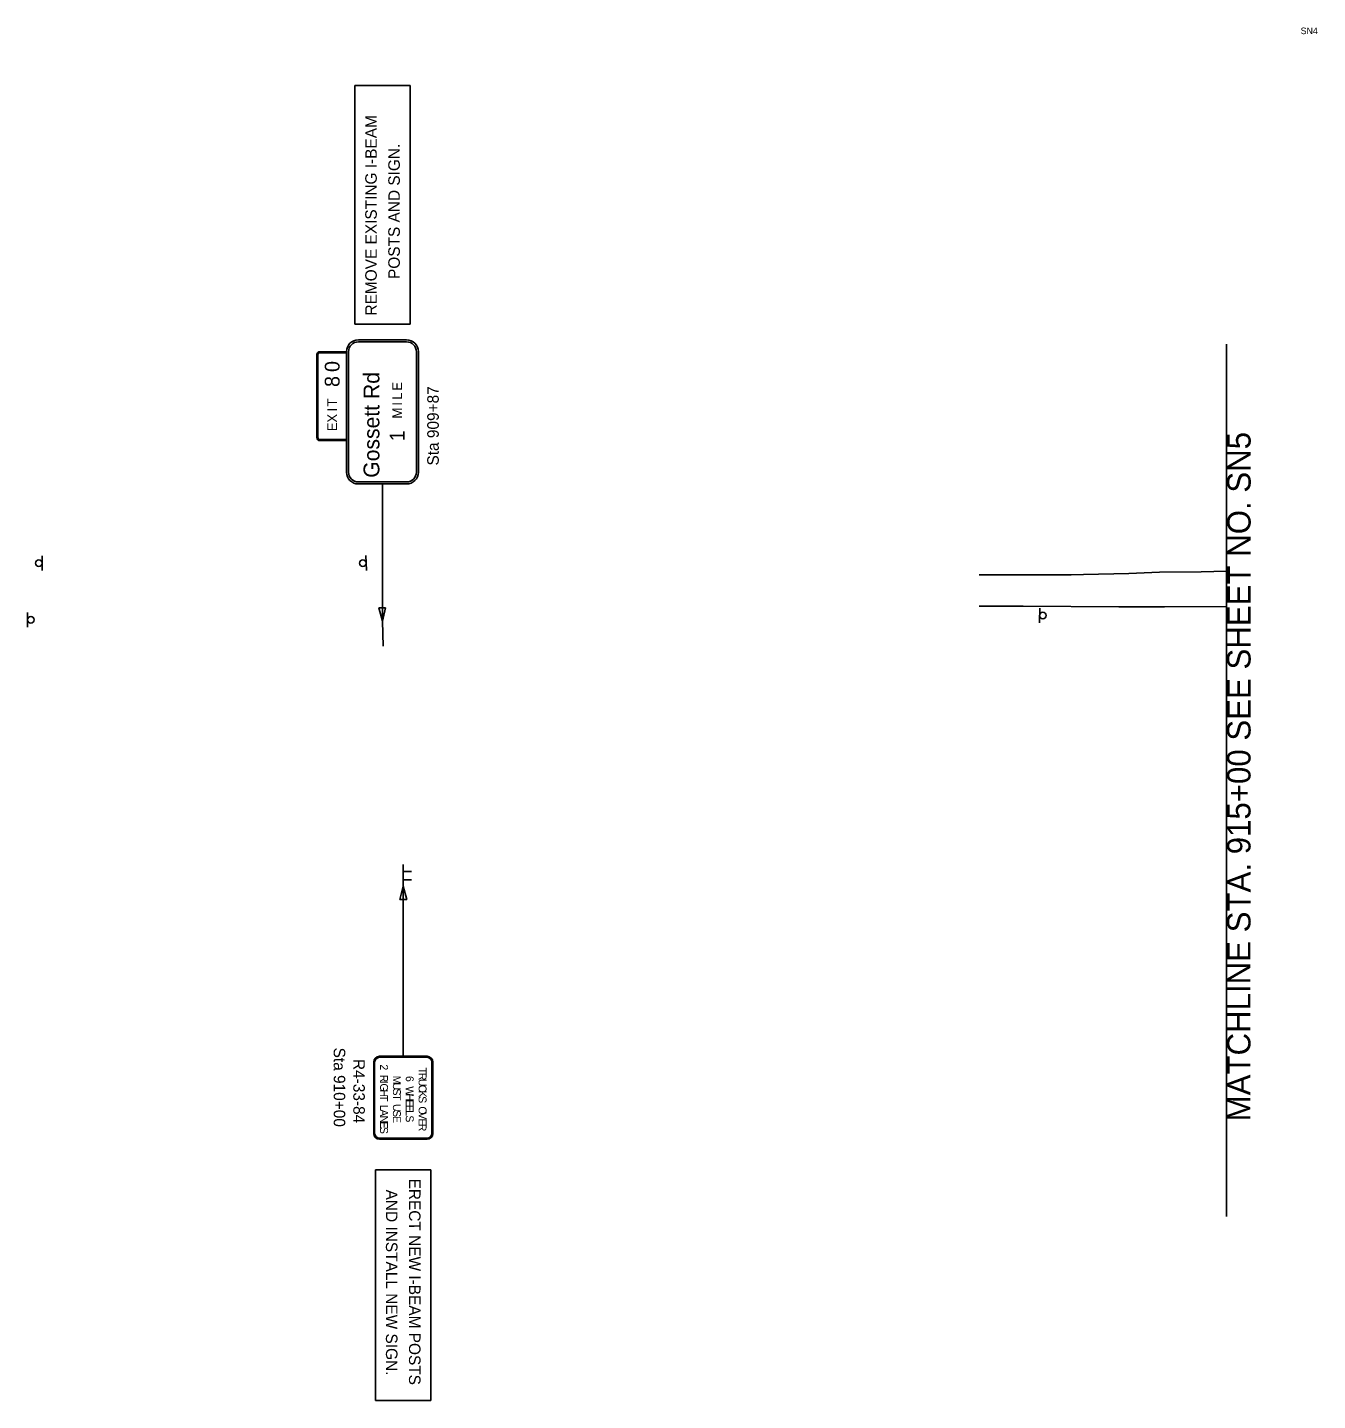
# Model space of a CAD drawing. Extents: x 1738774 to 1740359, y 1166808 to 1167650.
# Drawn here: x 1739575 to 1740359, y 1166808 to 1167642 of the extents above; entities that cross this region are included whole.
import ezdxf

# ---------------------------------------------------------------- set-up
doc = ezdxf.new("R2010")
doc.units = 0
for name, color, linetype in [('RD_EX_Road', 7, 'Continuous'), ('RD_SHT_MatchLine', 7, 'Continuous'), ('RD_SHT_TX', 7, 'Continuous'), ('SN_P_Signs', 7, 'Continuous')]:
    doc.layers.add(name, color=color, linetype=linetype)

msp = doc.modelspace()

# ---------------------------------------------------------------- linework, layer by layer
at = {"layer": 'RD_EX_Road'}
for points in [[(1740303.73, 1167311.86), (1740288.33, 1167311.47), (1740263.02, 1167311.09), (1740244.51, 1167310.39), (1740216.78, 1167309.74), (1740209.34, 1167309.56), (1740178.78, 1167309.55), (1740161.18, 1167309.54), (1740153.46, 1167309.6)], [(1740153.47, 1167290.46), (1740180.3, 1167290.45), (1740238.29, 1167290.17), (1740266.1, 1167290.17), (1740303.73, 1167290.28)]]:
    msp.add_lwpolyline(points, dxfattribs=at)
at = {"layer": 'RD_SHT_MatchLine'}
msp.add_lwpolyline([(1740303.73, 1166919.91), (1740303.73, 1167194.04), (1740303.73, 1167449.62)], dxfattribs=at)
at = {"layer": 'SN_P_Signs'}
for p, q in [((1739774.26, 1167461.8), (1739774.26, 1167606.82)), ((1739774.26, 1167606.82), (1739807.87, 1167606.82)), ((1739807.87, 1167606.82), (1739807.87, 1167461.8)), ((1739807.87, 1167461.8), (1739774.26, 1167461.8)), ((1739791.07, 1167364.75), (1739791.07, 1167281.39)), ((1739584.35, 1167312.12), (1739584.35, 1167321.12)), ((1739781.31, 1167312.23), (1739780.97, 1167321.23)), ((1740190.28, 1167289.39), (1740190.13, 1167280.39)), ((1739575.45, 1167286.77), (1739575.56, 1167277.77)), ((1739791.43, 1167266.17), (1739791.07, 1167281.39)), ((1739803.73, 1167120.52), (1739803.73, 1167133.56)), ((1739803.73, 1167129.45), (1739808.72, 1167129.45)), ((1739803.73, 1167124.43), (1739808.72, 1167124.43)), ((1739803.73, 1167017.16), (1739803.73, 1167120.52)), ((1739786.93, 1166808.11), (1739786.93, 1166948.13)), ((1739786.93, 1166948.13), (1739820.54, 1166948.13)), ((1739820.54, 1166948.13), (1739820.54, 1166808.11)), ((1739820.54, 1166808.11), (1739786.93, 1166808.11))]:
    msp.add_line(p, q, dxfattribs=at)
for points in [[(1739776.43, 1167452.27), (1739805.7, 1167452.27)], [(1739776.43, 1167451.07), (1739805.7, 1167451.07)], [(1739751.23, 1167392.87), (1739751.23, 1167443.27)], [(1739751.83, 1167443.27), (1739751.83, 1167392.87)], [(1739753.03, 1167445.07), (1739769.23, 1167445.07), (1739769.23, 1167444.47)], [(1739769.23, 1167444.47), (1739753.03, 1167444.47)], [(1739769.23, 1167371.95), (1739769.23, 1167445.07)], [(1739770.43, 1167371.95), (1739770.43, 1167445.07)], [(1739811.7, 1167445.07), (1739811.7, 1167371.95)], [(1739812.9, 1167445.07), (1739812.9, 1167371.95)], [(1739753.03, 1167391.67), (1739769.23, 1167391.67), (1739769.23, 1167391.07), (1739753.03, 1167391.07)], [(1739805.7, 1167365.95), (1739776.43, 1167365.95)], [(1739805.7, 1167364.75), (1739776.43, 1167364.75)], [(1739818.13, 1167017.16), (1739789.33, 1167017.16)], [(1739789.33, 1167016.56), (1739818.13, 1167016.56)], [(1739785.73, 1167013.56), (1739785.73, 1166970.36)], [(1739786.33, 1166970.36), (1739786.33, 1167013.56)], [(1739821.13, 1167013.56), (1739821.13, 1166970.36)], [(1739821.73, 1166970.36), (1739821.73, 1167013.56)], [(1739818.13, 1166967.36), (1739789.33, 1166967.36)], [(1739789.33, 1166966.76), (1739818.13, 1166966.76)]]:
    msp.add_lwpolyline(points, dxfattribs=at)
for points in [[(1739792.98, 1167289.62), (1739791.02, 1167281.39), (1739788.88, 1167289.57)], [(1739801.68, 1167112.32), (1739803.73, 1167120.52), (1739805.79, 1167112.32)]]:
    msp.add_lwpolyline(points, close=True, dxfattribs=at)
for centre in [(1739582.33, 1167316.64), (1739779.12, 1167316.67), (1739577.53, 1167282.28), (1740192.23, 1167284.84)]:
    msp.add_circle(centre, 2, dxfattribs=at)
for centre, radius, start, end in [((1739776.43, 1167445.07), 7.2, 90, 180), ((1739776.43, 1167445.07), 6, 90, 180), ((1739805.7, 1167445.07), 7.2, 360, 90), ((1739805.7, 1167445.07), 6, 360, 90), ((1739753.03, 1167443.27), 1.8, 90, 180), ((1739753.03, 1167443.27), 1.2, 90, 180), ((1739753.03, 1167392.87), 1.8, 180, 270), ((1739753.03, 1167392.87), 1.2, 180, 270), ((1739776.43, 1167371.95), 7.2, 180, 270), ((1739776.43, 1167371.95), 6, 180, 270), ((1739805.7, 1167371.95), 7.2, 270, 360), ((1739805.7, 1167371.95), 6, 270, 360), ((1739789.33, 1167013.56), 3.6, 90, 180), ((1739789.33, 1167013.56), 3, 90, 180), ((1739818.13, 1167013.56), 3.6, 360, 90), ((1739818.13, 1167013.56), 3, 360, 90), ((1739789.33, 1166970.36), 3.6, 180, 270), ((1739789.33, 1166970.36), 3, 180, 270), ((1739818.13, 1166970.36), 3.6, 270, 360), ((1739818.13, 1166970.36), 3, 270, 360)]:
    msp.add_arc(centre, radius, start, end, dxfattribs=at)

# ---------------------------------------------------------------- texts
at = {"layer": 'RD_SHT_TX'}
msp.add_text('SN4', height=4, dxfattribs=at).set_placement((1740348.78, 1167637.92))
msp.add_text('MATCHLINE STA. 915+00 SEE SHEET NO. SN5', height=14.1726, rotation=89.98556, dxfattribs=at).set_placement((1740318.28, 1166977.67))
at = {"layer": 'SN_P_Signs'}
for s, height, rotation, p in [('REMOVE EXISTING I-BEAM', 6.9998, 90.00008, (1739787.62, 1167467.03)), ('POSTS AND SIGN.', 6.9998, 90.00008, (1739801.62, 1167489.22)), ('0', 9, 90, (1739765.03, 1167432.72)), ('Gossett Rd', 9.6, 90, (1739789.2, 1167368.52)), ('8', 9, 90, (1739765.03, 1167423.62)), ('E', 6, 90, (1739803, 1167421.32)), ('Sta 909+87', 7, 90.00008, (1739825.28, 1167375.93)), ('T', 6, 90, (1739763.53, 1167411.75)), ('L', 6, 90, (1739803, 1167415.89)), ('I', 6, 90, (1739763.53, 1167408.77)), ('X', 6, 90, (1739763.53, 1167401.95)), ('I', 6, 90, (1739803, 1167412.3)), ('M', 6, 90, (1739803, 1167404.44)), ('E', 6, 90, (1739763.53, 1167396.8)), ('1', 9, 90, (1739804.5, 1167390.69)), ('Sta 910+00', 7, 270.00008, (1739761.46, 1167022.44)), ('R4-33-84', 7, 270.00008, (1739773.36, 1167015.55)), ('2', 4.8, 270, (1739789.63, 1167012.25)), ('T', 4.8, 270, (1739813.03, 1167010.33)), ('R', 4.8, 270, (1739813.03, 1167007.12)), ('G', 4.8, 270, (1739789.63, 1167000.7)), ('R', 4.8, 270, (1739789.63, 1167006.02)), ('I', 4.8, 270, (1739789.63, 1167002.39)), ('U', 4.8, 270, (1739797.43, 1167001.27)), ('M', 4.8, 270, (1739797.43, 1167005.4)), ('6', 4.8, 270, (1739805.23, 1167005.23)), ('W', 4.8, 270, (1739805.23, 1166999)), ('U', 4.8, 270, (1739813.03, 1167003.48)), ('C', 4.8, 270, (1739813.03, 1166999.85)), ('H', 4.8, 270, (1739789.63, 1166997.07)), ('T', 4.8, 270, (1739789.63, 1166993.63)), ('S', 4.8, 270, (1739797.43, 1166997.64)), ('T', 4.8, 270, (1739797.43, 1166994.2)), ('H', 4.8, 270, (1739805.23, 1166994.59)), ('E', 4.8, 270, (1739805.23, 1166990.95)), ('S', 4.8, 270, (1739813.03, 1166992.98)), ('K', 4.8, 270, (1739813.03, 1166996.41)), ('L', 4.8, 270, (1739789.63, 1166987.63)), ('A', 4.8, 270, (1739789.63, 1166984.96)), ('U', 4.8, 270, (1739797.43, 1166988.2)), ('S', 4.8, 270, (1739797.43, 1166984.56)), ('S', 4.8, 270, (1739805.23, 1166981.32)), ('E', 4.8, 270, (1739805.23, 1166987.74)), ('L', 4.8, 270, (1739805.23, 1166984.53)), ('O', 4.8, 270, (1739813.03, 1166986.75)), ('V', 4.8, 270, (1739813.03, 1166983.17)), ('S', 4.8, 270, (1739789.63, 1166974.3)), ('N', 4.8, 270, (1739789.63, 1166981.15)), ('E', 4.8, 270, (1739789.63, 1166977.51)), ('E', 4.8, 270, (1739797.43, 1166980.93)), ('E', 4.8, 270, (1739813.03, 1166979.43)), ('R', 4.8, 270, (1739813.03, 1166976.22)), ('ERECT NEW I-BEAM POSTS', 6.9998, 270.00008, (1739807.18, 1166942.9)), ('AND INSTALL NEW SIGN.', 6.9998, 270.00008, (1739793.18, 1166936.21))]:
    msp.add_text(s, height=height, rotation=rotation, dxfattribs=at).set_placement(p)

doc.saveas('drawing.dxf')
